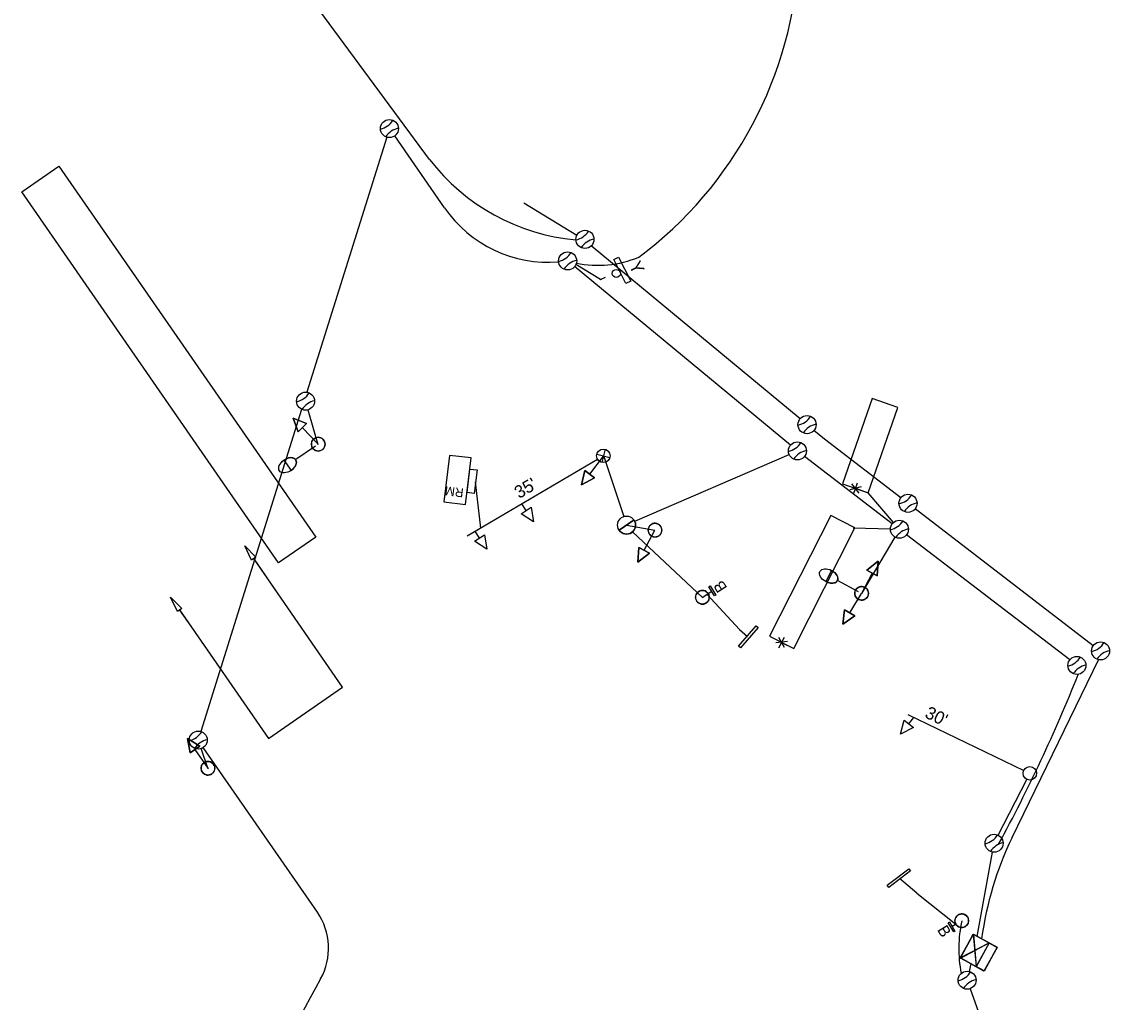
# Model space of a CAD drawing. Extents: x 596176 to 605330, y 332416 to 402398.
# Drawn here: x 602314.8 to 602556.7, y 357121.7 to 357338.9 of the extents above; entities that cross this region are included whole.
import ezdxf

# ---------------------------------------------------------------- set-up
doc = ezdxf.new("R2010")
doc.units = 0
for name, color, linetype in [('P_LTG', 7, 'Continuous'), ('P_MISC_TXT', 7, 'Continuous'), ('P_SIG', 7, 'Continuous'), ('P_SIG_Bold', 7, 'Continuous'), ('P_SIG_Conduit', 7, 'Continuous'), ('P_SIG_IC', 7, 'Continuous'), ('P_SIG_Loops', 7, 'Continuous')]:
    doc.layers.add(name, color=color, linetype=linetype)

# ---------------------------------------------------------------- blocks, each defined once
blk = doc.blocks.new('_U333')
at = {"layer": 'P_SIG_Bold'}
for p, q in [((-3.43, 0), (-0.11, 0)), ((-0.08, 0.08), (0.08, -0.08)), ((0.08, 0.08), (-0.08, -0.08))]:
    blk.add_line(p, q, dxfattribs=at)
blk.add_circle((0, 0), 0.114, dxfattribs=at)
blk.add_text("45'", height=0.213, dxfattribs=at).set_placement((-1.43, 0.09))
blk = doc.blocks.new('_U318')
at = {"layer": 'P_LTG'}
for p, q in [((4.32, 25.12), (-4.14, 25.12)), ((0.05, 2.3), (0.05, 18.44))]:
    blk.add_line(p, q, dxfattribs=at)
blk.add_ellipse((0.09, 25.12), major_axis=(0, 6.65), ratio=0.636439, dxfattribs=at)
blk.add_ellipse((0.09, 25.12), major_axis=(0, 6.65), ratio=0.636439, start_param=1.570796, end_param=4.712389, dxfattribs=at)
blk = doc.blocks.new('_U225')
at = {"layer": 'P_SIG'}
blk.add_circle((0, 0.01), 6.1, dxfattribs=at)
for centre, start, end in [((-15.46, 0.12), 336.67411, 22.52722), ((15.45, 0.15), 157.57508, 203.4282)]:
    blk.add_arc(centre, 13.28, start, end, dxfattribs=at)
blk = doc.blocks.new('CONTROL CABINET_7')
at = {"layer": 'P_SIG'}
for p, q in [((-0.229, 0.305), (0.229, 0.305)), ((-0.229, -0.152), (-0.229, 0.305)), ((0.229, 0.305), (0.229, -0.152)), ((-0.229, 0.152), (0.229, 0.152)), ((-0.229, -0.152), (0.229, 0.152)), ((0.229, -0.152), (-0.229, 0.152)), ((0.229, -0.152), (-0.229, -0.152))]:
    blk.add_line(p, q, dxfattribs=at)

msp = doc.modelspace()

# ---------------------------------------------------------------- linework, layer by layer
at = {"layer": 'P_SIG'}
for p, q in [((602445.97, 357286.23), (602447.03, 357286.78)), ((602448.68, 357280.88), (602445.97, 357286.23)), ((602447.03, 357286.78), (602449.75, 357281.42)), ((602449.75, 357281.42), (602448.68, 357280.88)), ((602376.95, 357248.96), (602380.46, 357245.31)), ((602440.64, 357238.66), (602443.71, 357242.68)), ((602416.48, 357226.73), (602415.35, 357237)), ((602426.55, 357230.6), (602425.57, 357232.08)), ((602447.17, 357226.25), (602450.47, 357228.51)), ((602416.21, 357224.52), (602415.23, 357226)), ((602452.72, 357221.8), (602455.11, 357226.26)), ((602503.21, 357216.76), (602500.9, 357212.26)), ((602465.58, 357211.36), (602467.68, 357212.71)), ((602473.85, 357204.28), (602466.63, 357212.04)), ((602498.28, 357207.94), (602500.9, 357212.26)), ((602473.85, 357204.28), (602475.65, 357202.7)), ((602511.39, 357183.35), (602512.51, 357184.73)), ((602353.15, 357177.66), (602356.03, 357173.5)), ((602513.18, 357145.82), (602509.3, 357149.05)), ((602513.18, 357145.82), (602521.81, 357138.93)), ((602521.83, 357138.94), (602520.98, 357138.42)), ((602522.8, 357131.45), (602525.66, 357136.72)), ((602525.66, 357136.72), (602530.93, 357133.86)), ((602525.66, 357136.72), (602526.32, 357129.54)), ((602522.8, 357131.45), (602529.17, 357134.82)), ((602529.17, 357134.82), (602526.32, 357129.54)), ((602530.93, 357133.86), (602528.07, 357128.59)), ((602528.07, 357128.59), (602522.8, 357131.45))]:
    msp.add_line(p, q, dxfattribs=at)
for points in [[(602445.97, 357286.23), (602447.03, 357286.78), (602449.75, 357281.42), (602448.68, 357280.88)], [(602409.55, 357242.82), (602408.31, 357232.55), (602413.1, 357231.98), (602414.33, 357242.25)], [(602415.03, 357234.38), (602413.45, 357234.58), (602414.08, 357239.81), (602415.66, 357239.62)], [(602428.19, 357228.14), (602425.45, 357229.87), (602427.65, 357231.33)], [(602417.84, 357222.06), (602415.11, 357223.79), (602417.3, 357225.25)], [(602468.33, 357211.7), (602467.03, 357213.72), (602467.31, 357213.9), (602468.61, 357211.88)], [(602473.59, 357200.57), (602477.56, 357205.07), (602478.01, 357204.67), (602474.04, 357200.17)], [(602509.51, 357181.06), (602510.37, 357184.19), (602512.41, 357182.52)], [(602511.72, 357150.75), (602506.96, 357147.09), (602506.6, 357147.57), (602511.36, 357151.22)], [(602520.35, 357139.44), (602521.6, 357137.39), (602521.33, 357137.22), (602520.07, 357139.27)]]:
    msp.add_lwpolyline(points, close=True, dxfattribs=at)
for points in [[(602374.9, 357251.09), (602377.9, 357249.87), (602376, 357248.04), (602374.9, 357251.09)], [(602377.9, 357249.87), (602374.9, 357251.09), (602376, 357248.04), (602377.9, 357249.87)], [(602438.85, 357236.3), (602439.59, 357239.45), (602441.69, 357237.86), (602438.85, 357236.3)], [(602438.85, 357236.3), (602439.59, 357239.45), (602441.69, 357237.86), (602438.85, 357236.3)], [(602439.59, 357239.45), (602438.85, 357236.3), (602441.69, 357237.86), (602439.59, 357239.45)], [(602450.47, 357228.51), (602447.17, 357226.25)], [(602451.32, 357219.19), (602451.55, 357222.42), (602453.88, 357221.18), (602451.32, 357219.19)], [(602451.55, 357222.42), (602451.32, 357219.19), (602453.88, 357221.18), (602451.55, 357222.42)], [(602504.55, 357219.4), (602504.38, 357216.17), (602502.03, 357217.36), (602504.55, 357219.4)], [(602504.38, 357216.17), (602504.55, 357219.4), (602502.03, 357217.36), (602504.38, 357216.17)], [(602496.75, 357205.4), (602497.15, 357208.62), (602499.41, 357207.26), (602496.75, 357205.4)], [(602496.75, 357205.4), (602497.15, 357208.62), (602499.41, 357207.26), (602496.75, 357205.4)], [(602497.15, 357208.62), (602496.75, 357205.4), (602499.41, 357207.26), (602497.15, 357208.62)], [(602351.46, 357180.09), (602354.23, 357178.41), (602352.07, 357176.9), (602351.46, 357180.09)], [(602354.23, 357178.41), (602351.46, 357180.09), (602352.07, 357176.9), (602354.23, 357178.41)]]:
    msp.add_lwpolyline(points, dxfattribs=at)
for centre, radius in [((602396.26, 357315.24), 2), ((602435.75, 357285.93), 2), ((602446.53, 357283.14), 0.9), ((602377.66, 357254.84), 2), ((602380.46, 357245.31), 1.52), ((602380.46, 357245.31), 1.52), ((602380.46, 357245.31), 1.52), ((602486.68, 357243.82), 2), ((602448.82, 357227.38), 2), ((602455.11, 357226.26), 1.52), ((602455.11, 357226.26), 1.52), ((602455.11, 357226.26), 1.52), ((602509.3, 357226.46), 2), ((602500.9, 357212.26), 1.52), ((602500.9, 357212.26), 1.52), ((602500.9, 357212.26), 1.52), ((602465.61, 357211.38), 1.52), ((602548.63, 357196.29), 2), ((602353.86, 357179.74), 2), ((602356.03, 357173.5), 1.52), ((602356.03, 357173.5), 1.52), ((602356.03, 357173.5), 1.52), ((602530.28, 357156.89), 2), ((602523.11, 357139.72), 1.52), ((602524.29, 357126.54), 2)]:
    msp.add_circle(centre, radius, dxfattribs=at)
for centre, radius, start, end in [((602393.33, 357319.39), 4.36, 282.2572, 328.1103), ((602399.11, 357311.05), 4.36, 101.3562, 147.2093), ((602432.82, 357290.08), 4.36, 282.2572, 328.1103), ((602438.6, 357281.74), 4.36, 101.3562, 147.2093), ((602374.74, 357258.98), 4.36, 282.2572, 328.1103), ((602380.51, 357250.65), 4.36, 101.3562, 147.2093), ((602380.46, 357245.31), 1.52, 313.9518, 133.9518), ((602380.46, 357245.31), 1.52, 133.9518, 313.9518), ((602483.75, 357247.97), 4.36, 282.2572, 328.1103), ((602489.53, 357239.63), 4.36, 101.3562, 147.2093), ((602448.82, 357227.38), 2, 304.6821, 34.3829), ((602455.11, 357226.26), 1.52, 61.9575, 241.9575), ((602455.11, 357226.26), 1.52, 241.9575, 61.9575), ((602506.38, 357230.61), 4.36, 282.2572, 328.1103), ((602448.82, 357227.38), 2, 214.3829, 304.6821), ((602512.15, 357222.27), 4.36, 101.3562, 147.2093), ((602500.9, 357212.26), 1.52, 63.0248, 243.0248), ((602500.9, 357212.26), 1.52, 243.0248, 63.0248), ((602465.61, 357211.38), 1.52, 67.1809, 247.1809), ((602465.61, 357211.38), 1.52, 247.1809, 67.1809), ((602545.71, 357200.43), 4.36, 282.2572, 328.1103), ((602551.49, 357192.1), 4.36, 101.3562, 147.2093), ((602350.94, 357183.89), 4.36, 282.2572, 328.1103), ((602356.72, 357175.55), 4.36, 101.3562, 147.2093), ((602356.03, 357173.5), 1.52, 124.7799, 304.7799), ((602356.03, 357173.5), 1.52, 304.7799, 124.7799), ((602527.36, 357161.04), 4.36, 282.2572, 328.1103), ((602533.14, 357152.7), 4.36, 101.3562, 147.2093), ((602523.11, 357139.72), 1.52, 39.6959, 219.6959), ((602523.11, 357139.72), 1.52, 219.6959, 39.6959), ((602521.37, 357130.68), 4.36, 282.2572, 328.1103), ((602527.14, 357122.35), 4.36, 101.3562, 147.2093)]:
    msp.add_arc(centre, radius, start, end, dxfattribs=at)
at = {"layer": 'P_SIG_Bold'}
for p, q in [((602442.22, 357243.1), (602445.13, 357242.34)), ((602444.05, 357244.17), (602443.3, 357241.27)), ((602413.5, 357224.98), (602442.38, 357241.96)), ((602511.15, 357185.38), (602536.84, 357173.03))]:
    msp.add_line(p, q, dxfattribs=at)
for centre in [(602443.67, 357242.72), (602538.19, 357172.38)]:
    msp.add_circle(centre, 1.5, dxfattribs=at)
at = {"layer": 'P_SIG_Conduit'}
for p, q in [((602395.66, 357313.34), (602377.97, 357256.81)), ((602485.14, 357245.1), (602437.29, 357284.66)), ((602443.05, 357281.79), (602437.57, 357285.12)), ((602376.79, 357253.03), (602354.46, 357181.65)), ((602378.2, 357252.91), (602380.35, 357245.23)), ((602443.66, 357242.83), (602448.19, 357229.28)), ((602450.63, 357228.23), (602484.84, 357243.03)), ((602507.71, 357227.68), (602488.26, 357242.61)), ((602448.83, 357227.39), (602455.11, 357226.26)), ((602465.66, 357211.3), (602450.14, 357225.88)), ((602547.05, 357197.5), (602510.89, 357225.25)), ((602508.28, 357224.74), (602500.9, 357212.26)), ((602356.03, 357173.5), (602354.51, 357177.85)), ((602531.19, 357158.67), (602537.52, 357171.04)), ((602526.55, 357136.24), (602529.93, 357154.92)), ((602524.79, 357128.47), (602525.22, 357130.14))]:
    msp.add_line(p, q, dxfattribs=at)
for points in [[(602408.46, 357297.68), (602397.42, 357313.62)], [(602380.27, 357141.58), (602355, 357178.1)], [(602524.96, 357124.65), (602542.53, 357075.51)]]:
    msp.add_lwpolyline(points, dxfattribs=at)
for centre, radius, start, end in [((602398.62, 357357.71), 88.5, 306.6886, 357.2473), ((602431.48, 357313.61), 28, 214.6821, 274.6677), ((602442.49, 357308.37), 23.43, 258.1678, 292.6114), ((602211.9, 357329.17), 363, 331.6225, 338.1903), ((602368.76, 357133.62), 14, 331.0197, 34.6821), ((602551.61, 357133.52), 29.17, 167.7207, 190.845), ((602786.9, 356902.02), 464, 151.0197, 155.7252)]:
    msp.add_arc(centre, radius, start, end, dxfattribs=at)
at = {"layer": 'P_SIG_IC'}
for points in [[(602405.14, 357308.41), (602379.59, 357343.03)], [(602437.77, 357291.52), (602426.06, 357298.75)], [(602487.27, 357250.91), (602440.97, 357289.25)], [(602509.6, 357233.42), (602492.7, 357246.41), (602490.35, 357248.36)], [(602552.24, 357200.64), (602512.77, 357230.98)], [(602534.26, 357158.15), (602553.51, 357197.67)]]:
    msp.add_lwpolyline(points, dxfattribs=at)
for centre, radius, start, end in [((602441.83, 357336.7), 46.33, 217.6309, 264.6908), ((602601.6, 357125.63), 74.78, 154.2191, 172.2395)]:
    msp.add_arc(centre, radius, start, end, dxfattribs=at)
at = {"layer": 'P_SIG_Loops'}
for p, q in [((602500.8, 357235.86), (602498.28, 357235.22)), ((602500.33, 357234.48), (602498.75, 357236.53)), ((602499.09, 357234.22), (602499.97, 357236.75)), ((602499.53, 357235.53), (602502.36, 357234.54)), ((602508, 357227.98), (602502.36, 357234.54)), ((602499.07, 357226.81), (602507.3, 357226.53)), ((602484.49, 357201.56), (602481.9, 357201.27)), ((602483.84, 357200.26), (602482.54, 357202.5)), ((602482.58, 357200.17), (602483.79, 357202.56)), ((602483.18, 357201.4), (602485.86, 357200.05))]:
    msp.add_line(p, q, dxfattribs=at)
for points in [[(602314.77, 357301.26), (602322.99, 357306.95), (602379.9, 357224.72), (602371.67, 357219.03), (602314.77, 357301.26)], [(602349.71, 357208.59), (602369.42, 357180.11), (602385.86, 357191.49), (602366.17, 357219.95)], [(602366.19, 357219.93), (602368.8, 357216.15)], [(602349.74, 357208.55), (602352.35, 357204.77)]]:
    msp.add_lwpolyline(points, dxfattribs=at)
for points in [[(602502.36, 357234.54), (602508.95, 357253.42), (602503.28, 357255.4), (602496.7, 357236.51)], [(602485.86, 357200.05), (602499.44, 357226.8), (602494.09, 357229.51), (602480.51, 357202.76)], [(602365.71, 357219.6), (602364.19, 357222.81), (602366.67, 357220.26)], [(602349.26, 357208.22), (602347.75, 357211.43), (602350.22, 357208.88)]]:
    msp.add_lwpolyline(points, close=True, dxfattribs=at)

# ---------------------------------------------------------------- block references
at = {"layer": 'P_LTG', "xscale": 0.32808333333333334}
for name, p, yscale, rotation in [('_U333', (602443.07, 357281.77), 0.3280833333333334, -155.84643614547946), ('_U318', (602380.46, 357245.31), 0.3280833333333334, 124.68212460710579), ('_U318', (602500.9, 357212.26), 0.32808333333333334, 62.435578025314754), ('_U333', (602356.03, 357173.5), 0.3280833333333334, -55.31787539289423)]:
    msp.add_blockref(name, p, dxfattribs=dict(at, yscale=yscale, rotation=rotation))
at = {"layer": 'P_MISC_TXT', "xscale": 13.123333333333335, "yscale": 13.123333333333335, "rotation": -118.98465916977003}
msp.add_blockref('CONTROL CABINET_7', (602525.99, 357133.13), dxfattribs=at)
at = {"layer": 'P_SIG', "xscale": 13.123333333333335, "yscale": 13.123333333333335, "rotation": -119.0529008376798}
msp.add_blockref('CONTROL CABINET_7', (602525.99, 357133.13), dxfattribs=at)
at = {"layer": 'P_SIG_IC', "xscale": 0.3280833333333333, "yscale": 0.32808333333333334, "rotation": 124.5442935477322}
for p in [(602439.59, 357290.7), (602488.81, 357249.64), (602511.19, 357232.21), (602553.88, 357199.5)]:
    msp.add_blockref('_U225', p, dxfattribs=at)

# ---------------------------------------------------------------- texts
at = {"layer": 'P_SIG'}
for s, height, rotation, p in [('Y', 2.8, 296.8728, (602449.26, 357284.95)), ('RM', 2, 173.1428, (602412.79, 357235.5)), ('B', 2.52, 122.7164, (602471.21, 357213.47)), ('B', 2.52, 301.5335, (602517.57, 357137.71))]:
    msp.add_text(s, height=height, rotation=rotation, dxfattribs=at).set_placement(p)
at = {"layer": 'P_SIG_Bold'}
for s, rotation, p in [("35'", 30.4459, (602424.99, 357233.15)), ("30'", 334.3347, (602514.72, 357184.84))]:
    msp.add_text(s, height=2.8, rotation=rotation, dxfattribs=at).set_placement(p)

doc.saveas('drawing.dxf')
